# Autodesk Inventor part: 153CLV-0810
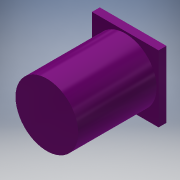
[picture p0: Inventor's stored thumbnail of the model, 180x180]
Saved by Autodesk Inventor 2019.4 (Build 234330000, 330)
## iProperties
Created: 2019-11
Part Number: 153CLV-0810
Material: Generic
Document SubType Name: Modeling
Designer: Willist
Density: 1 g/cm^3
Appearance: 153CLV-0810, 153CLV-0810
Author: Willist
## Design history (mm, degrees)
sketch "153CLV-0810, 153CLV-0810_22"
  geometry: L1 (-4.302, 4.2)-(4.2, 4.2); L2 (4.2, 4.2)-(4.2, -4.302); L3 (4.2, -4.302)-(-4.302, -4.302); L4 (-4.302, -4.302)-(-4.302, 4.2)
  constraints: 8 end point
extrude "Extrusion1" join sketch "153CLV-0810, 153CLV-0810_22" distance "d0" = 1; taper "d1" = 0 deg
sketch "Sketch2"
  geometry: L1 (-4.302, 4.2)-(-4.302, -4.302) reference; L2 (4.2, 4.2)-(-4.302, 4.2) reference; L3 (-4.302, -4.302)-(4.2, -4.302); L4 (4.2, -4.302)-(4.2, 4.2); L5 (4.2, 4.2)-(-4.302, 4.2); L6 (-4.302, 4.2)-(-4.302, -4.302); C1 r 4 at (-0.051, -0.051); 1 further point
  constraints: 8 end point, 2 parallel, 1 centre point, 1 horizontal, 1 perpendicular
  dimensions: "d2" = 8 diameter of C1
extrude "Extrusion2" join sketch "Sketch2" distance "d3" = 10; taper "d4" = 0 deg
body "Solid1"
